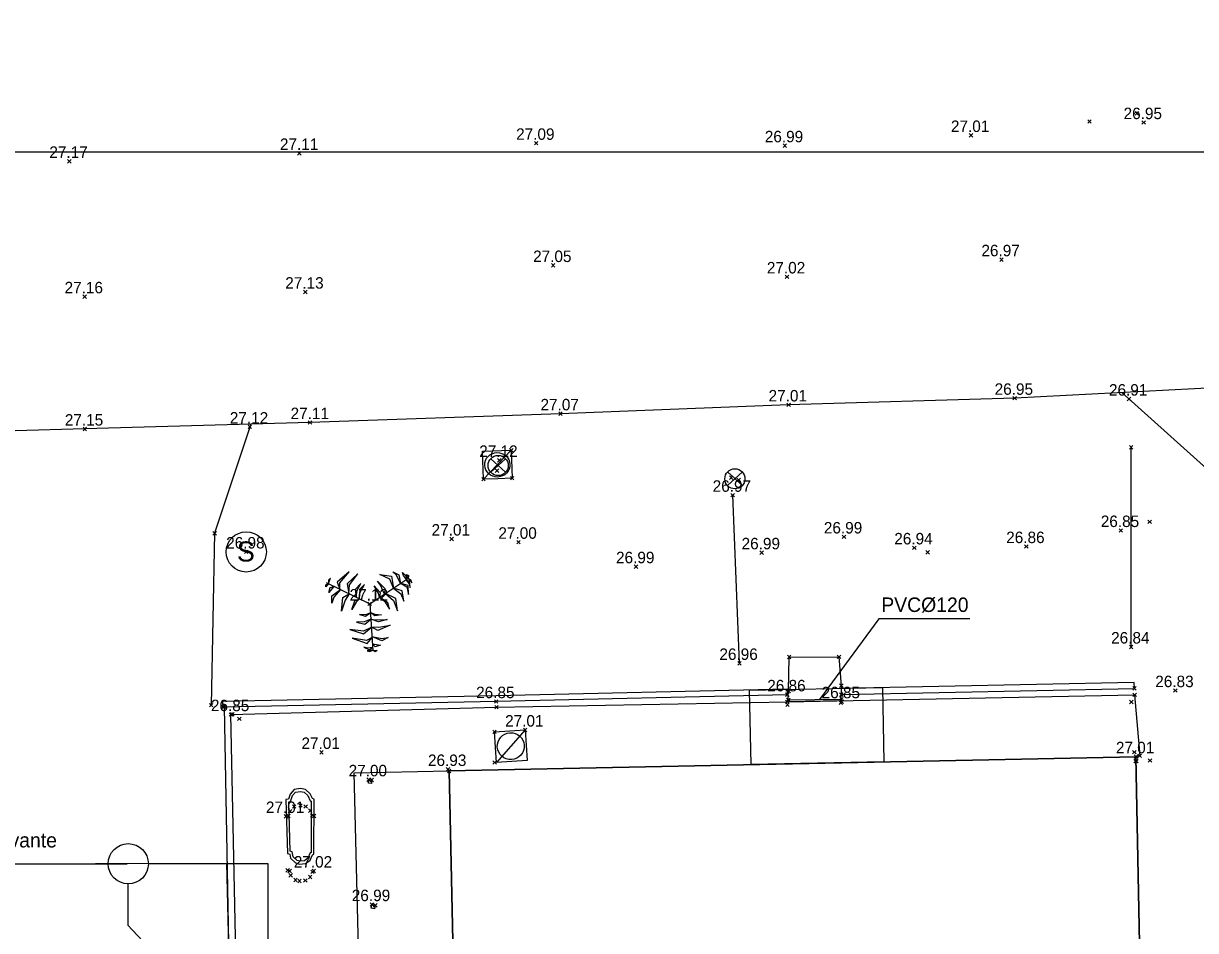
# Model space of a CAD drawing. Extents: x 37864 to 38032, y 453991 to 454052.
# Drawn here: x 37894.08 to 37923.19, y 454028.87 to 454051.41 of the extents above; entities that cross this region are included whole.
import ezdxf

# ---------------------------------------------------------------- set-up
doc = ezdxf.new("R2010")
doc.units = 0
for name, color, linetype in [('DH_CALCUL SURFACE-TEXTE', 7, 'Continuous'), ('GO MUR EXTERIEUR', 7, 'Continuous'), ('GO_MUR_INTERIEUR', 7, 'Continuous'), ('GO_POTEAU', 7, 'Continuous'), ('PS_Bolt', 7, 'Continuous'), ('PS_Const', 7, 'Continuous'), ('PS_Dim', 7, 'Continuous'), ('PS_Elev_flag', 7, 'Continuous'), ('PS_Hatch', 7, 'Continuous'), ('PS_Hidden', 7, 'Continuous'), ('PS_Mid', 7, 'Continuous'), ('PS_Object', 7, 'Continuous'), ('PS_Plate', 7, 'Continuous'), ('PS_Solid', 7, 'Continuous'), ('PS_Text', 7, 'Continuous'), ('SO_MENUISERIE EXT DOR', 7, 'Continuous'), ('SO_MENUISERIE INT DOR', 7, 'Continuous'), ('SO_SANITAIRE DETAILLE', 7, 'Continuous')]:
    doc.layers.add(name, color=color, linetype=linetype)

# ---------------------------------------------------------------- blocks, each defined once
blk = doc.blocks.new('PANNEAU')
blk.add_circle((0, 0), 0.5)
blk.add_text('S', height=0.5).set_placement((-0.233, -0.24))
blk = doc.blocks.new('A-REGARD')
for p, q in [((0, 1), (1, 1)), ((0, 0), (1, 1)), ((0, 0), (0, 1)), ((1, 1), (1, 0)), ((0.5, 0), (0, 0)), ((1, 0), (0.5, 0))]:
    blk.add_line(p, q)
blk.add_circle((0.5, 0.5), 0.438)
blk = doc.blocks.new('CONIFERE')
for p, q in [((0, 0), (0.976, 0.647)), ((-1.078, 0.532), (0, 0)), ((0, 0), (0.08, -1.165))]:
    blk.add_line(p, q)
for points in [[(-1.025, 0.504), (-0.971, 0.637), (-1.021, 0.589)], [(-0.741, 0.364), (-0.739, 0.523), (-0.511, 0.797), (-0.811, 0.54)], [(-0.519, 0.261), (-0.499, 0.472), (-0.295, 0.746), (-0.559, 0.501)], [(0.588, 0.387), (0.498, 0.618), (0.255, 0.727), (0.538, 0.69)], [(0.768, 0.507), (0.663, 0.715), (0.579, 0.797), (0.722, 0.721)], [(0.913, 0.604), (0.84, 0.707), (0.816, 0.777), (0.899, 0.693)], [(0.907, 0.587), (0.977, 0.501), (1.009, 0.403), (0.992, 0.558)], [(0.956, 0.633), (0.917, 0.732), (0.966, 0.705)], [(0.958, 0.634), (1.046, 0.52), (1.029, 0.588)], [(-1.023, 0.503), (-1.089, 0.42), (-1.091, 0.475)], [(-0.888, 0.436), (-1.016, 0.279), (-0.985, 0.411)], [(-0.721, 0.354), (-0.891, 0.168), (-0.941, 0.021), (-0.939, 0.198)], [(-0.335, 0.164), (-0.311, 0.342), (-0.22, 0.506), (-0.364, 0.356)], [(-0.262, 0.122), (-0.241, 0.278), (-0.128, 0.485), (-0.248, 0.367)], [(0.245, 0.158), (0.215, 0.27), (0.111, 0.452), (0.259, 0.279)], [(0.371, 0.242), (0.267, 0.463), (0.197, 0.562), (0.378, 0.385)], [(0.59, 0.394), (0.775, 0.253), (0.851, 0.066), (0.809, 0.322)], [(0.782, 0.51), (0.919, 0.422), (0.966, 0.236), (0.956, 0.46)], [(-0.506, 0.248), (-0.606, 0.089), (-0.702, -0.183), (-0.666, 0.155)], [(-0.256, 0.125), (-0.338, 0.043), (-0.443, -0.139), (-0.368, 0.076)], [(0.246, 0.164), (0.37, 0.069), (0.493, -0.134), (0.451, 0.03)], [(0.394, 0.257), (0.593, 0.086), (0.691, -0.173), (0.65, 0.13)], [(0.018, -0.223), (-0.1, -0.27), (-0.255, -0.267), (-0.103, -0.306)], [(0.018, -0.218), (0.131, -0.256), (0.297, -0.27), (0.128, -0.295)], [(0.029, -0.381), (-0.138, -0.448), (-0.325, -0.452), (-0.124, -0.502)], [(0.029, -0.376), (0.157, -0.398), (0.437, -0.392), (0.22, -0.442)], [(0.041, -0.571), (0.229, -0.578), (0.512, -0.525), (0.202, -0.663)], [(0.037, -0.588), (-0.156, -0.676), (-0.495, -0.637), (-0.152, -0.743)], [(0.058, -0.832), (-0.08, -0.91), (-0.431, -0.849), (-0.059, -0.981)], [(0.057, -0.81), (0.303, -0.864), (0.456, -0.834), (0.301, -0.92)], [(0.064, -1.081), (-0.046, -1.098), (-0.147, -1.076), (-0.004, -1.14)], [(0.079, -1.149), (-0.063, -1.168), (0.004, -1.187)], [(0.069, -0.995), (0.269, -1.028), (0.14, -1.067)], [(0.079, -1.146), (0.184, -1.162), (0.137, -1.191)]]:
    blk.add_lwpolyline(points, close=True)
blk = doc.blocks.new('BORNANTI')
for p, q in [((-0.369, -0.338), (0.369, 0.338)), ((-0.369, 0.338), (0.369, -0.338))]:
    blk.add_line(p, q)
blk.add_circle((0, 0), 0.5)
blk = doc.blocks.new('POINT_DISPLAY')
for p, q in [((-0.04375, -0.04375), (0.04375, 0.04375)), ((-0.04375, 0.04375), (0.04375, -0.04375))]:
    blk.add_line(p, q)
blk = doc.blocks.new('POINTCOT')
blk.add_blockref('POINT_DISPLAY', (0, 0))
blk = doc.blocks.new('DIVERS-P')
blk.add_circle((0, 0), 0.5)

msp = doc.modelspace()

# ---------------------------------------------------------------- linework, layer by layer
at = {"layer": 'DEFPOINTS'}
msp.add_lwpolyline([(37864.064, 453990.816), (37946.064, 453990.816), (37946.064, 454048.216), (37864.064, 454048.216)], close=True, dxfattribs=at)
at = {"layer": 'GO MUR EXTERIEUR'}
msp.add_lwpolyline([(37904.652, 454032.841), (37904.92, 454020.167), (37902.603, 454020.093), (37902.686, 454016.74), (37922.017, 454017.171), (37921.708, 454033.195)], close=True, dxfattribs=at)
at = {"layer": 'GO_MUR_INTERIEUR'}
msp.add_line((37913.073, 454034.608), (37914.394, 454034.623), dxfattribs=at)
msp.add_lwpolyline([(37899.06, 454034.436), (37899.21, 454026.312), (37899.534, 454016.645)], dxfattribs=at)
at = {"layer": 'PS_Bolt'}
for points in [[(37901.289, 454030.778), (37901.296, 454032.142), (37901.252, 454032.154), (37901.197, 454032.273), (37901.084, 454032.381), (37900.956, 454032.405), (37900.8, 454032.378), (37900.699, 454032.264), (37900.659, 454032.143), (37900.596, 454032.132), (37900.637, 454030.793), (37900.69, 454030.777), (37900.713, 454030.67), (37900.835, 454030.554), (37900.932, 454030.525), (37901.08, 454030.541), (37901.197, 454030.626), (37901.255, 454030.756), (37901.289, 454030.778)], [(37900.668, 454032.074), (37900.713, 454032.082), (37900.761, 454032.228), (37900.836, 454032.313), (37900.955, 454032.334), (37901.051, 454032.316), (37901.139, 454032.232), (37901.202, 454032.094), (37901.225, 454032.088), (37901.22, 454030.816), (37901.2, 454030.804), (37901.141, 454030.672), (37901.054, 454030.609), (37900.938, 454030.596), (37900.871, 454030.616), (37900.777, 454030.706), (37900.749, 454030.832), (37900.705, 454030.845), (37900.668, 454032.074)]]:
    msp.add_lwpolyline(points, dxfattribs=at)
at = {"layer": 'PS_Dim'}
for p, q in [((37890.702, 454030.534), (37896.649, 454030.534)), ((37900.154, 454030.534), (37897.196, 454030.534)), ((37900.154, 454020.093), (37900.154, 454030.534))]:
    msp.add_line(p, q, dxfattribs=at)
at = {"layer": 'PS_Hatch'}
msp.add_lwpolyline([(37912.111, 454034.846), (37915.411, 454034.915), (37915.449, 454033.065), (37912.15, 454032.997)], close=True, dxfattribs=at)
msp.add_lwpolyline([(37902.603, 454020.093), (37902.29, 454032.792), (37904.652, 454032.841), (37904.92, 454020.167), (37902.603, 454020.093)], dxfattribs=at)
at = {"layer": 'PS_Mid'}
for points in [[(37913.094, 454035.67), (37914.331, 454035.675), (37914.389, 454034.958), (37914.381, 454034.585), (37913.059, 454034.558), (37913.082, 454034.829), (37913.094, 454035.67)], [(37902.686, 454016.74), (37902.53, 454016.739), (37899.575, 454016.672), (37899.397, 454026.348), (37899.231, 454034.242), (37905.827, 454034.425), (37913.049, 454034.558), (37921.676, 454034.732), (37921.802, 454033.217), (37921.708, 454033.195)]]:
    msp.add_lwpolyline(points, dxfattribs=at)
at = {"layer": 'PS_Object'}
msp.add_lwpolyline([(37889.343, 454030.528), (37899.117, 454030.549), (37899.54, 454012.849), (37895.242, 454006.442), (37895.242, 454005.264), (37889.943, 454005.178)], dxfattribs=at)
at = {"layer": 'PS_Solid'}
msp.add_lwpolyline([(37914.392, 454034.736), (37921.671, 454034.892), (37921.667, 454035.042), (37914.388, 454034.886)], close=True, dxfattribs=at)
for points in [[(37899.03, 454034.578), (37905.815, 454034.715), (37913.046, 454034.884), (37913.049, 454034.734), (37905.818, 454034.565), (37899.033, 454034.428), (37899.03, 454034.578)], [(37921.708, 454033.195), (37922.017, 454017.171), (37902.686, 454016.74), (37902.603, 454020.093), (37904.92, 454020.167), (37904.652, 454032.841), (37921.708, 454033.195)]]:
    msp.add_lwpolyline(points, dxfattribs=at)
at = {"layer": 'PS_Text'}
for points in [[(37902.651, 454032.624), (37902.728, 454032.617), (37902.721, 454032.527), (37902.643, 454032.534)], [(37902.73, 454029.522), (37902.815, 454029.502), (37902.795, 454029.415), (37902.71, 454029.434)]]:
    msp.add_lwpolyline(points, close=True, dxfattribs=at)
at = {"layer": 'SO_MENUISERIE INT DOR'}
msp.add_lwpolyline([(37917.585, 454036.616), (37915.324, 454036.616), (37913.845, 454034.617)], dxfattribs=at)
at = {"layer": 'SO_SANITAIRE DETAILLE'}
for p, q in [((37921.59, 454035.922), (37921.59, 454040.88)), ((37911.86, 454035.515), (37911.693, 454039.692)), ((37896.668, 454030.034), (37896.668, 454029.009)), ((37896.668, 454029.009), (37899.21, 454026.312))]:
    msp.add_line(p, q, dxfattribs=at)
for points in [[(37931.461, 454051.412), (37931.46, 454048.283), (37931.063, 454042.806), (37929.02, 454042.628), (37924.438, 454042.4), (37918.697, 454042.102), (37913.082, 454041.936), (37907.417, 454041.715), (37901.195, 454041.497), (37895.602, 454041.336), (37888.675, 454041.141), (37884.765, 454041.024), (37878.173, 454040.907), (37873.078, 454041.057), (37866.515, 454040.532)], [(37921.361, 454042.24), (37924.438, 454039.473), (37928.39, 454036.508), (37931.87, 454034.006), (37934.645, 454032.123), (37937.958, 454030.315)], [(37899.722, 454041.454), (37898.825, 454038.745), (37898.738, 454034.476)]]:
    msp.add_lwpolyline(points, dxfattribs=at)

# ---------------------------------------------------------------- block references
at = {"layer": 'DH_CALCUL SURFACE-TEXTE', "rotation": 2.2526485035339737e-05}
for p in [(37920.556, 454048.975), (37921.73, 454049.18), (37921.9, 454048.951), (37917.611, 454048.631), (37906.811, 454048.436), (37912.988, 454048.375), (37900.93, 454048.185), (37895.218, 454047.988), (37918.368, 454045.543), (37907.233, 454045.4), (37913.039, 454045.117), (37895.596, 454044.623), (37901.077, 454044.739), (37913.082, 454041.936), (37918.697, 454042.102), (37921.537, 454042.082), (37907.417, 454041.715), (37899.7, 454041.388), (37901.195, 454041.497), (37895.602, 454041.336), (37906.195, 454040.806), (37921.59, 454040.88), (37905.895, 454040.559), (37905.839, 454040.3), (37905.502, 454040.088), (37906.216, 454040.113), (37911.656, 454040.126), (37911.839, 454040.073), (37911.693, 454039.692), (37922.051, 454039.029), (37898.825, 454038.745), (37921.333, 454038.816), (37904.712, 454038.604), (37906.371, 454038.525), (37914.455, 454038.656), (37899.61, 454038.283), (37912.412, 454038.263), (37916.204, 454038.385), (37916.537, 454038.272), (37918.984, 454038.417), (37909.293, 454037.917), (37902.676, 454036.991), (37921.59, 454035.922), (37913.094, 454035.67), (37914.331, 454035.675), (37911.86, 454035.515), (37914.389, 454034.958), (37913.049, 454034.734), (37913.082, 454034.829), (37914.392, 454034.736), (37921.671, 454034.892), (37921.676, 454034.732), (37922.686, 454034.838), (37898.738, 454034.476), (37899.033, 454034.428), (37899.06, 454034.436), (37905.818, 454034.565), (37905.827, 454034.425), (37913.049, 454034.558), (37913.054, 454034.489), (37913.073, 454034.608), (37914.38, 454034.539), (37914.394, 454034.623), (37914.399, 454034.563), (37921.595, 454034.555), (37899.231, 454034.242), (37899.267, 454034.249), (37899.438, 454034.136), (37905.776, 454033.811), (37906.538, 454033.859), (37901.48, 454033.304), (37921.666, 454033.306), (37921.708, 454033.195), (37921.802, 454033.217), (37905.78, 454033.052), (37921.703, 454033.085), (37921.72, 454033.083), (37922.057, 454033.101), (37902.651, 454032.624), (37902.728, 454032.617), (37904.622, 454032.88), (37904.652, 454032.841), (37900.699, 454031.842), (37900.8, 454031.957), (37900.956, 454031.983), (37901.084, 454031.959), (37901.197, 454031.852), (37900.596, 454031.711), (37900.659, 454031.722), (37901.252, 454031.732), (37901.296, 454031.721), (37900.637, 454030.372), (37900.69, 454030.356), (37901.255, 454030.335), (37901.289, 454030.356), (37900.713, 454030.249), (37900.835, 454030.133), (37900.932, 454030.104), (37901.08, 454030.12), (37901.197, 454030.205), (37902.73, 454029.522), (37902.815, 454029.502)]:
    msp.add_blockref('POINTCOT', p, dxfattribs=at)
at = {"layer": 'PS_Bolt', "xscale": 0.5000000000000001, "yscale": 0.5, "rotation": 2.2526485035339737e-05}
for p in [(37905.867, 454040.429), (37911.748, 454040.099)]:
    msp.add_blockref('BORNANTI', p, dxfattribs=at)
at = {"layer": 'PS_Const', "rotation": 2.2526485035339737e-05}
msp.add_blockref('CONIFERE', (37902.676, 454036.991), dxfattribs=at)
at = {"layer": 'PS_Elev_flag', "rotation": 2.2526485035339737e-05}
msp.add_blockref('PANNEAU', (37899.61, 454038.283), dxfattribs=at)
at = {"layer": 'PS_Plate', "rotation": 2.2526485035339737e-05}
msp.add_blockref('DIVERS-P', (37896.68, 454030.534), dxfattribs=at)
at = {"layer": 'SO_MENUISERIE EXT DOR'}
for p, xscale, yscale, rotation in [((37905.502, 454040.088), 0.7140624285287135, 0.6935784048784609, 1.9842813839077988), ((37906.538, 454033.859), 0.7636120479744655, 0.7597857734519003, -176.444621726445)]:
    msp.add_blockref('A-REGARD', p, dxfattribs=dict(at, xscale=xscale, yscale=yscale, rotation=rotation))

# ---------------------------------------------------------------- texts
at = {"layer": 'GO_POTEAU'}
for s, p in [('26.95', (37921.402, 454049.034)), ('27.01', (37917.113, 454048.715)), ('27.09', (37906.313, 454048.52)), ('26.99', (37912.49, 454048.459)), ('27.11', (37900.447, 454048.269)), ('27.17', (37894.72, 454048.072)), ('27.05', (37906.735, 454045.484)), ('26.97', (37917.87, 454045.627)), ('27.02', (37912.541, 454045.201)), ('27.16', (37895.098, 454044.707)), ('27.13', (37900.579, 454044.823)), ('27.01', (37912.584, 454042.02)), ('26.95', (37918.199, 454042.185)), ('26.91', (37921.039, 454042.166)), ('27.07', (37906.919, 454041.799)), ('27.15', (37895.104, 454041.42)), ('27.12', (37899.202, 454041.471)), ('27.11', (37900.712, 454041.581)), ('27.12', (37905.397, 454040.643)), ('26.97', (37911.195, 454039.776)), ('26.85', (37920.835, 454038.9)), ('27.01', (37904.214, 454038.688)), ('27.00', (37905.873, 454038.609)), ('26.99', (37913.957, 454038.74)), ('26.86', (37918.486, 454038.501)), ('26.98', (37899.112, 454038.367)), ('26.99', (37911.914, 454038.347)), ('26.94', (37915.706, 454038.469)), ('26.99', (37908.795, 454038.001)), ('27.12', (37902.178, 454037.075)), ('26.84', (37921.092, 454036.006)), ('26.96', (37911.362, 454035.599)), ('26.86', (37912.551, 454034.818)), ('26.83', (37922.188, 454034.922)), ('26.85', (37905.32, 454034.649)), ('26.85', (37913.901, 454034.647)), ('26.85', (37898.733, 454034.326)), ('27.01', (37906.04, 454033.943)), ('27.01', (37900.982, 454033.387)), ('27.01', (37921.21, 454033.279)), ('26.93', (37904.124, 454032.964)), ('27.00', (37902.153, 454032.707)), ('27.01', (37900.098, 454031.795)), ('27.02', (37900.791, 454030.44)), ('26.99', (37902.232, 454029.606))]:
    msp.add_text(s, height=0.285, rotation=0, dxfattribs=at).set_placement(p)
at = {"layer": 'PS_Hidden'}
msp.add_text('Barrière levante', height=0.36, rotation=360, dxfattribs=at).set_placement((37891.51, 454030.94))
at = {"layer": 'SO_MENUISERIE INT DOR'}
msp.add_text('PVC%%C120', height=0.36, rotation=0, dxfattribs=at).set_placement((37915.383, 454036.79))

doc.saveas('drawing.dxf')
